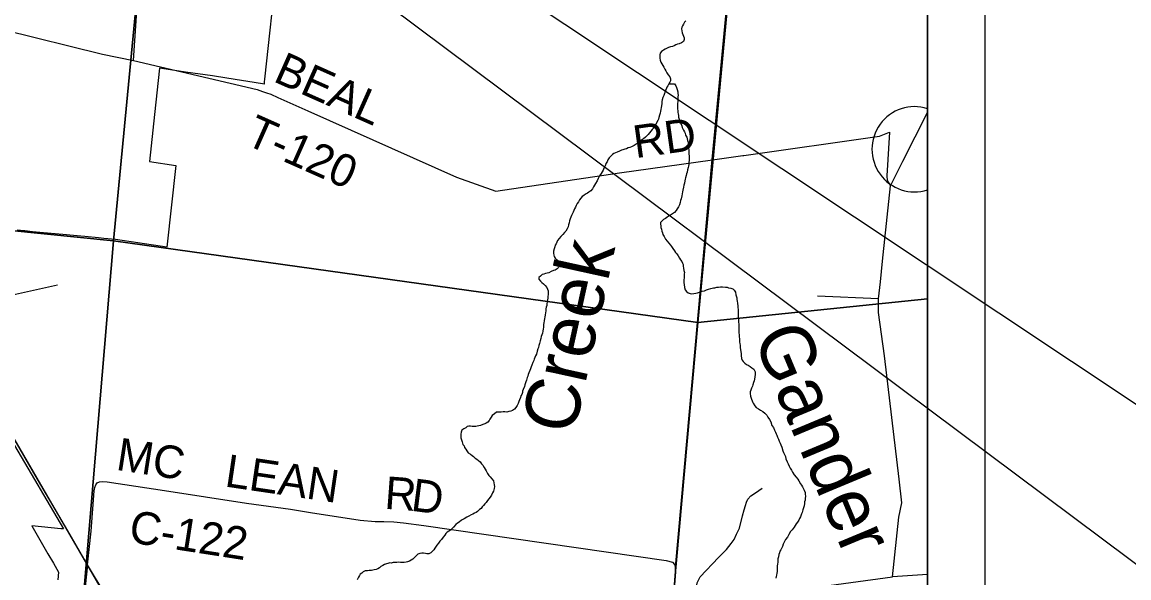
# Model space of a CAD drawing. Extents: x -7.3 to 34, y 0 to 22.
# Drawn here: x 7.321 to 9.251, y 15.258 to 16.227 of the extents above; entities that cross this region are included whole.
import ezdxf

# ---------------------------------------------------------------- set-up
doc = ezdxf.new("R2010")
doc.units = 0
for name, color, linetype in [('GM_X_City_Street', 7, 'Continuous'), ('GM_X_Corporation', 7, 'Continuous'), ('GM_X_County_Road', 7, 'Continuous'), ('GM_X_County_Road_Text', 7, 'Continuous'), ('GM_X_Minor_River', 7, 'Continuous'), ('GM_X_Minor_River_Text', 7, 'Continuous'), ('GM_X_Rail_Line', 7, 'Continuous'), ('GM_X_State_Route', 7, 'Continuous'), ('GM_X_Township_Road', 7, 'Continuous'), ('GM_X_Township_Road_Text', 7, 'Continuous'), ('GM_X_Township_Text', 7, 'Continuous'), ('GM_X_Unincorporated_Location', 7, 'Continuous'), ('SH_Data', 7, 'Continuous'), ('SH_Text', 7, 'Continuous')]:
    doc.layers.add(name, color=color, linetype=linetype)

msp = doc.modelspace()

# ---------------------------------------------------------------- linework, layer by layer
at = {"layer": 'GM_X_City_Street'}
for points in [[(7.515, 16.1606), (7.5352, 16.4637), (7.5353, 16.4644), (7.5529, 16.6394)], [(6.8397, 16.3042), (6.9163, 16.2969), (6.9632, 16.2927), (6.978, 16.2913), (6.9879, 16.2949), (6.9944, 16.3002), (7, 16.3085), (7.0054, 16.3187), (7.0196, 16.3167), (7.0985, 16.2937), (7.1289, 16.2841), (7.1663, 16.2709), (7.1875, 16.2621), (7.2672, 16.2205), (7.2871, 16.2145), (7.4609, 16.1716), (7.515, 16.1606)]]:
    msp.add_lwpolyline(points, dxfattribs=at)
at = {"layer": 'GM_X_Corporation'}
for points in [[(8.9, 14.1), (8.9, 19.7858), (8.8913, 19.7872), (7.8469, 19.8978), (7.6051, 19.9224), (6.9988, 19.9839), (6.9507, 19.9888), (6.4242, 20.0024), (6.4154, 20.0027), (6.0763, 20.0096), (6.0677, 20.0098), (6.0214, 20.0108), (5.9388, 20.0125), (5.8024, 20.0153), (4.9519, 20.0328), (4.9401, 20.0331), (4.9235, 20.0334), (4.7954, 20.036), (4.4762, 20.0428), (4.2328, 20.0479), (4.2288, 20.048), (2.7422, 20.0783)], [(8.9, 14.1), (8.9, 19.3924)], [(8.6707, 17.5268), (8.6269, 17.0745), (8.6205, 17.0074), (8.6201, 16.9946), (8.6191, 16.9835), (8.5243, 15.9875), (8.46, 15.2759), (8.4601, 15.2687), (8.4562, 15.2161)], [(8.4562, 15.2161), (8.4601, 15.2687), (8.46, 15.2759), (8.5243, 15.9875), (8.6191, 16.9835), (8.6201, 16.9946), (8.6205, 17.0074), (8.6269, 17.0745), (8.6707, 17.5268)], [(7.7646, 16.3262), (7.7435, 16.1277), (7.743, 16.123), (7.7427, 16.1193), (7.7398, 16.1197), (7.6775, 16.1295), (7.6527, 16.1334), (7.6058, 16.1398), (7.5868, 16.1429), (7.583, 16.1435), (7.5793, 16.1441), (7.5603, 16.1472), (7.5517, 16.0661), (7.5429, 15.984), (7.5888, 15.9773), (7.573, 15.8344), (7.4836, 15.8479), (7.4632, 15.8499), (7.4537, 15.8507), (7.4301, 15.853), (7.4166, 15.8542), (7.3913, 15.8566), (7.3781, 15.8578), (7.3648, 15.8591), (7.3516, 15.8603), (7.3384, 15.8615), (7.3252, 15.8628), (7.3244, 15.8629), (7.312, 15.864)], [(7.3075, 15.4887), (7.3926, 15.3428), (7.388, 15.3433), (7.3373, 15.3484), (7.3656, 15.2997), (7.3751, 15.2833), (7.3841, 15.2677), (7.3828, 15.254)]]:
    msp.add_lwpolyline(points, dxfattribs=at)
for points in [[(7.5781, 16.8709), (7.4799, 15.8457), (6.4371, 15.9508), (6.5281, 16.9583)], [(8.5942, 16.7168), (8.4992, 15.7029), (7.4799, 15.8457), (7.5781, 16.8709)], [(8.9, 15.7443), (8.9, 16.7566), (8.5942, 16.7168), (8.4992, 15.7029)], [(6.4371, 15.9508), (7.4799, 15.8457), (7.3939, 14.8252), (6.3438, 14.9266)], [(7.4799, 15.8457), (8.4992, 15.7029), (8.4066, 14.6743), (7.3939, 14.8252)], [(8.9, 14.7231), (8.9, 15.7443), (8.4992, 15.7029), (8.4066, 14.6743)]]:
    msp.add_lwpolyline(points, close=True, dxfattribs=at)
at = {"layer": 'GM_X_County_Road'}
for points in [[(7.4344, 15.2802), (7.4407, 15.3391), (7.4465, 15.4096), (7.4474, 15.4153), (7.4491, 15.4201), (7.4516, 15.4234), (7.4554, 15.425), (7.4599, 15.4256), (7.4688, 15.4252), (7.5687, 15.4099), (7.7121, 15.3879), (7.7885, 15.3774), (7.8235, 15.3715), (7.9102, 15.3583), (7.9361, 15.3559), (7.9516, 15.3559), (7.9688, 15.3553), (7.9859, 15.3538), (8.0212, 15.3491), (8.444, 15.2881), (8.4549, 15.285), (8.4585, 15.2807), (8.4599, 15.2763)], [(7.4344, 15.2802), (7.4256, 15.1989), (7.4002, 14.9537), (7.3569, 14.4092), (7.3329, 14.1292), (7.3296, 14.1)], [(8.4599, 15.2763), (8.4602, 15.2754), (8.4603, 15.2681), (8.4564, 15.2156)]]:
    msp.add_lwpolyline(points, dxfattribs=at)
at = {"layer": 'GM_X_Minor_River'}
for points in [[(8.478, 16.2297), (8.4757, 16.2271), (8.4741, 16.224), (8.4722, 16.2211), (8.4714, 16.2184), (8.4709, 16.2158), (8.4712, 16.2123), (8.4719, 16.2085), (8.473, 16.2055), (8.4741, 16.2028), (8.4751, 16.2001), (8.4754, 16.1967), (8.4739, 16.1937), (8.4704, 16.1911), (8.4666, 16.1896), (8.4635, 16.1886), (8.4608, 16.1875), (8.4578, 16.186), (8.4547, 16.185), (8.4516, 16.1839), (8.4482, 16.1828), (8.4455, 16.1817), (8.4421, 16.1803), (8.439, 16.1785), (8.4355, 16.1759), (8.4336, 16.1729), (8.4328, 16.1702), (8.4331, 16.1668), (8.4326, 16.1642), (8.4337, 16.1607), (8.4347, 16.1573), (8.4362, 16.1546), (8.438, 16.1515), (8.4399, 16.1484), (8.4417, 16.145), (8.4435, 16.1423), (8.4453, 16.1388), (8.4475, 16.1353), (8.4501, 16.1319), (8.4516, 16.1284), (8.4515, 16.125), (8.4503, 16.1224), (8.4487, 16.1194), (8.4468, 16.1164), (8.4448, 16.1137), (8.444, 16.1103), (8.442, 16.1073), (8.4408, 16.1028), (8.4396, 16.0994), (8.4383, 16.096), (8.4371, 16.0919), (8.4363, 16.0885), (8.4362, 16.0851), (8.4358, 16.0813), (8.4353, 16.0782), (8.4345, 16.0748), (8.434, 16.0718), (8.4332, 16.0684), (8.432, 16.065), (8.4311, 16.0609), (8.4303, 16.0582), (8.4291, 16.0556), (8.4271, 16.0518), (8.4252, 16.0477), (8.4228, 16.0436), (8.4197, 16.0402), (8.4173, 16.0368), (8.415, 16.0339), (8.4127, 16.0312), (8.4076, 16.0264), (8.4042, 16.0238), (8.4011, 16.0212), (8.3984, 16.0186), (8.3945, 16.0161), (8.3918, 16.0142), (8.3883, 16.012), (8.3834, 16.0095), (8.3803, 16.0084), (8.3776, 16.0077), (8.3746, 16.0062), (8.3719, 16.0055), (8.3685, 16.0045), (8.3658, 16.0038), (8.3623, 16.0023), (8.3585, 16.0005)], [(8.4487, 16.1194), (8.4582, 16.1195), (8.4608, 16.1164), (8.4622, 16.113), (8.4633, 16.1095), (8.464, 16.1057), (8.4643, 16.1027), (8.4646, 16.1), (8.4642, 16.097), (8.4645, 16.0932), (8.464, 16.0894), (8.4635, 16.0848), (8.4634, 16.0814), (8.4638, 16.0788), (8.4637, 16.0757), (8.464, 16.0727), (8.4643, 16.0696), (8.4646, 16.067), (8.4653, 16.0643), (8.4657, 16.0616), (8.4667, 16.0578), (8.4678, 16.0547), (8.4689, 16.0513), (8.471, 16.0463), (8.4721, 16.0436), (8.4743, 16.039), (8.4757, 16.036), (8.4768, 16.0333), (8.4779, 16.0302), (8.4797, 16.0264), (8.4804, 16.0237), (8.4811, 16.021), (8.4822, 16.0176), (8.4824, 16.0134), (8.4831, 16.01), (8.4831, 16.0069), (8.4834, 16.0043), (8.4837, 16.0001), (8.4836, 15.997), (8.4839, 15.994), (8.4842, 15.989), (8.4841, 15.9864), (8.4837, 15.9822), (8.4832, 15.9788), (8.4828, 15.9762), (8.482, 15.9735), (8.4811, 15.9694), (8.4803, 15.9652), (8.4794, 15.9625), (8.479, 15.9599), (8.4778, 15.9557), (8.4773, 15.9531), (8.4765, 15.9505), (8.4757, 15.9463), (8.4748, 15.9429), (8.474, 15.9395), (8.4728, 15.9342), (8.4723, 15.9312), (8.4719, 15.9278), (8.471, 15.924), (8.4701, 15.9191), (8.4689, 15.916), (8.4681, 15.9126), (8.4669, 15.9085), (8.4653, 15.9051), (8.4633, 15.9014), (8.4614, 15.8987), (8.4586, 15.895), (8.4552, 15.8928), (8.4517, 15.8906), (8.4479, 15.8884), (8.4452, 15.8865), (8.4425, 15.8847), (8.4394, 15.8829), (8.4367, 15.8803), (8.4343, 15.8777), (8.4343, 15.8746), (8.4346, 15.872), (8.4349, 15.8689), (8.4356, 15.8659), (8.4363, 15.8624), (8.4374, 15.8594), (8.4381, 15.8567), (8.4403, 15.8532), (8.4428, 15.8486), (8.4458, 15.8451), (8.4487, 15.8413), (8.4517, 15.8382), (8.4535, 15.8355), (8.4554, 15.8324), (8.4583, 15.8281), (8.4601, 15.8254), (8.4624, 15.8227), (8.4646, 15.8196), (8.4671, 15.8154), (8.469, 15.8127), (8.4712, 15.8096), (8.4723, 15.8069), (8.4733, 15.8043), (8.4736, 15.8012), (8.4743, 15.7978)], [(8.3585, 16.0005), (8.3558, 15.9994), (8.3528, 15.998), (8.3501, 15.9965), (8.3466, 15.9928), (8.3446, 15.9902), (8.3423, 15.9868), (8.3411, 15.9834), (8.3387, 15.9804), (8.3379, 15.9778), (8.3367, 15.9751), (8.3351, 15.9725), (8.3339, 15.9691), (8.332, 15.9661), (8.3304, 15.9631), (8.3276, 15.959), (8.3253, 15.9545), (8.3233, 15.9504), (8.3209, 15.9455), (8.3189, 15.9425), (8.3174, 15.9398), (8.3154, 15.9365), (8.3127, 15.9331), (8.3092, 15.9305), (8.3065, 15.9287), (8.3034, 15.9269), (8.3004, 15.925), (8.2973, 15.9232), (8.2949, 15.9202), (8.293, 15.9172), (8.291, 15.9138), (8.2887, 15.9105), (8.2871, 15.9071), (8.2859, 15.9044), (8.2843, 15.9014), (8.2827, 15.8984), (8.2819, 15.8958), (8.2807, 15.8932), (8.2787, 15.8898), (8.2775, 15.8871), (8.2763, 15.8841), (8.2755, 15.8807), (8.2747, 15.8773), (8.2734, 15.8736), (8.273, 15.8701), (8.2714, 15.8664), (8.269, 15.8626), (8.2667, 15.86), (8.2636, 15.8567), (8.2601, 15.8533), (8.257, 15.8496), (8.2546, 15.8462), (8.2531, 15.8432), (8.2519, 15.8406), (8.2503, 15.838), (8.2495, 15.8349), (8.2483, 15.8316), (8.2474, 15.8278), (8.2473, 15.8244), (8.248, 15.8209), (8.2487, 15.8182), (8.2502, 15.8156), (8.2535, 15.8124), (8.2557, 15.8094), (8.2576, 15.8059), (8.2579, 15.8025), (8.2563, 15.7991), (8.2536, 15.7965), (8.2501, 15.7947), (8.2474, 15.7936), (8.2432, 15.7922), (8.2394, 15.79), (8.2363, 15.7893), (8.2337, 15.7886), (8.2306, 15.7875), (8.2279, 15.7868), (8.2245, 15.7842), (8.2221, 15.7816), (8.2217, 15.7786), (8.2246, 15.7751), (8.2273, 15.7731), (8.2302, 15.7704), (8.2328, 15.7677), (8.2358, 15.7642), (8.2372, 15.7611), (8.2379, 15.7585), (8.2382, 15.755), (8.2382, 15.7516), (8.2377, 15.749), (8.2373, 15.7456), (8.2368, 15.7425), (8.2364, 15.7391), (8.2359, 15.7357), (8.2355, 15.7327), (8.2347, 15.7297), (8.2342, 15.727), (8.2341, 15.7236), (8.2333, 15.7202), (8.2328, 15.7164), (8.232, 15.7126), (8.2316, 15.71)], [(8.4743, 15.7978), (8.475, 15.794), (8.4757, 15.7905), (8.4756, 15.7879), (8.4756, 15.7845), (8.4751, 15.781), (8.475, 15.7776), (8.475, 15.775), (8.4749, 15.7723), (8.4752, 15.7696), (8.4759, 15.7643), (8.4773, 15.7601), (8.4795, 15.757), (8.4821, 15.7547), (8.4855, 15.7535), (8.4881, 15.753), (8.4923, 15.7537), (8.4958, 15.7544), (8.4984, 15.7547), (8.5042, 15.7565), (8.5068, 15.7576), (8.5106, 15.7586), (8.5141, 15.7601), (8.5175, 15.7611), (8.5221, 15.7622), (8.5263, 15.7636), (8.529, 15.7639), (8.5324, 15.7646), (8.5354, 15.7649), (8.5385, 15.7652), (8.5419, 15.7652), (8.5472, 15.765), (8.5502, 15.7646), (8.5529, 15.7638), (8.5566, 15.7633), (8.56, 15.7621), (8.5626, 15.7598), (8.5648, 15.7559), (8.5655, 15.7517), (8.5669, 15.7464), (8.5672, 15.7437), (8.5679, 15.7399), (8.5682, 15.7372), (8.5688, 15.7308), (8.5694, 15.7243), (8.5694, 15.7209), (8.5697, 15.7163), (8.5696, 15.7125), (8.5699, 15.7083), (8.5701, 15.7041), (8.5704, 15.6996), (8.5704, 15.6969), (8.5706, 15.6901), (8.5709, 15.687), (8.5711, 15.6798), (8.5717, 15.673), (8.572, 15.6691), (8.5724, 15.6665), (8.5727, 15.6631), (8.573, 15.6593), (8.5733, 15.6554), (8.574, 15.6524), (8.5746, 15.6482), (8.5749, 15.6455), (8.5756, 15.6402), (8.5767, 15.6375), (8.5785, 15.6348), (8.5811, 15.6321), (8.5841, 15.6298), (8.5871, 15.6286), (8.5904, 15.6262), (8.5934, 15.6242), (8.5968, 15.6215), (8.599, 15.6169), (8.5993, 15.6127), (8.5988, 15.6078), (8.5975, 15.6014), (8.5963, 15.5983), (8.5951, 15.5946), (8.5943, 15.5919), (8.593, 15.5885), (8.5918, 15.5851), (8.5906, 15.5821), (8.5902, 15.5795), (8.5908, 15.5745), (8.5919, 15.5711), (8.5944, 15.5649), (8.5955, 15.5623), (8.5988, 15.5576), (8.601, 15.5549), (8.6048, 15.5522), (8.6085, 15.5502), (8.6126, 15.5478), (8.616, 15.5451), (8.6193, 15.5416), (8.6215, 15.5381), (8.6241, 15.5339), (8.6263, 15.5297), (8.6284, 15.5232), (8.631, 15.5201), (8.6328, 15.5151)], [(8.2316, 15.71), (8.2311, 15.7062), (8.2306, 15.7024), (8.2302, 15.6997), (8.2302, 15.6971), (8.2297, 15.6944), (8.2293, 15.6918), (8.2288, 15.688), (8.228, 15.6846), (8.2272, 15.6819), (8.226, 15.6786), (8.2251, 15.6755), (8.2243, 15.6714), (8.223, 15.6665), (8.2218, 15.6631), (8.2214, 15.6597), (8.2202, 15.657), (8.2189, 15.6529), (8.2177, 15.648), (8.2161, 15.645), (8.2149, 15.6419), (8.2137, 15.6393), (8.2129, 15.6367), (8.2113, 15.6333), (8.2097, 15.6288), (8.2085, 15.6257), (8.2073, 15.6224), (8.2061, 15.6193), (8.2045, 15.6152), (8.2033, 15.6122), (8.2025, 15.6095), (8.2016, 15.6069), (8.2004, 15.6024), (8.1992, 15.5997), (8.1976, 15.5941), (8.1971, 15.5914), (8.1947, 15.5862), (8.1935, 15.5835), (8.1931, 15.5809), (8.1919, 15.5775), (8.1903, 15.5749), (8.1899, 15.5722), (8.1879, 15.5684), (8.1867, 15.5651), (8.1855, 15.562), (8.1839, 15.5583), (8.1819, 15.5549), (8.1796, 15.5519), (8.1761, 15.5497), (8.1731, 15.5486), (8.1696, 15.5476), (8.1658, 15.5469), (8.1624, 15.547), (8.1594, 15.547), (8.1559, 15.5467), (8.1533, 15.5468), (8.1506, 15.5468), (8.148, 15.5465), (8.1445, 15.5439), (8.1403, 15.5406), (8.1387, 15.538), (8.1363, 15.5346), (8.1351, 15.532), (8.1328, 15.5294), (8.1301, 15.5272), (8.1274, 15.5261), (8.124, 15.525), (8.1198, 15.5236), (8.1171, 15.5229), (8.1144, 15.5222), (8.1118, 15.5219), (8.1091, 15.5215), (8.1053, 15.5216), (8.1027, 15.522), (8.0997, 15.5221), (8.097, 15.5218), (8.0943, 15.5196), (8.0908, 15.5177), (8.0877, 15.5152), (8.0865, 15.5118), (8.0857, 15.508), (8.0856, 15.5046), (8.0859, 15.5019), (8.087, 15.4981), (8.0881, 15.495), (8.0895, 15.4904), (8.0913, 15.4877), (8.0924, 15.485), (8.0942, 15.482), (8.0961, 15.4789), (8.0986, 15.4758), (8.1024, 15.4734), (8.1054, 15.4711), (8.108, 15.4691), (8.111, 15.4664), (8.1136, 15.4648), (8.1166, 15.4621), (8.1192, 15.4598), (8.1221, 15.4567), (8.1243, 15.454), (8.1265, 15.4501)], [(8.6328, 15.5151), (8.6346, 15.512), (8.6357, 15.509), (8.6371, 15.5063), (8.6382, 15.5032), (8.6397, 15.4998), (8.6411, 15.4963), (8.6429, 15.4925), (8.644, 15.4894), (8.6454, 15.4856), (8.6475, 15.4791), (8.6486, 15.476), (8.6508, 15.4718), (8.6519, 15.4691), (8.6529, 15.4653), (8.6551, 15.4599), (8.6565, 15.4565), (8.6583, 15.4523), (8.6602, 15.4492), (8.6628, 15.4457), (8.6642, 15.4422), (8.6671, 15.4376), (8.6704, 15.4334), (8.6738, 15.4299), (8.6756, 15.4268), (8.6782, 15.4218), (8.68, 15.4191), (8.6818, 15.4164), (8.6837, 15.413), (8.6847, 15.4103), (8.6862, 15.4064), (8.6865, 15.4034), (8.6868, 15.4003), (8.6863, 15.3958), (8.6863, 15.3931), (8.6854, 15.3901), (8.685, 15.3875), (8.6845, 15.3833), (8.6833, 15.3795), (8.6825, 15.3761), (8.6809, 15.3716), (8.68, 15.369), (8.678, 15.3641), (8.6765, 15.3611), (8.6753, 15.358), (8.6729, 15.3547), (8.6706, 15.3517), (8.669, 15.3491), (8.667, 15.3461), (8.6635, 15.3416), (8.6608, 15.3382), (8.658, 15.3333), (8.6553, 15.3288), (8.6521, 15.3244), (8.6506, 15.321), (8.6478, 15.3161), (8.6466, 15.3123), (8.6454, 15.3097), (8.6438, 15.3067), (8.6422, 15.3041), (8.6414, 15.3014), (8.6406, 15.2984), (8.6397, 15.2942), (8.6389, 15.2905), (8.6388, 15.2874), (8.6384, 15.2848), (8.6379, 15.2814), (8.6375, 15.2783), (8.6374, 15.2745), (8.6373, 15.2719), (8.6373, 15.2685), (8.6368, 15.2658), (8.6364, 15.2624), (8.6356, 15.2598), (8.6351, 15.2571)], [(8.1265, 15.4501), (8.1284, 15.447), (8.1302, 15.444), (8.1324, 15.4397), (8.1346, 15.4363), (8.1368, 15.4336), (8.1398, 15.4304), (8.1427, 15.427), (8.1434, 15.4235), (8.1441, 15.4201), (8.1444, 15.4167), (8.1439, 15.4133), (8.1427, 15.4087), (8.1411, 15.4057), (8.1395, 15.402), (8.1372, 15.3986), (8.1348, 15.3956), (8.1321, 15.3926), (8.1301, 15.3892), (8.1274, 15.3866), (8.1255, 15.384), (8.1231, 15.3814), (8.1212, 15.3784), (8.1181, 15.3766), (8.115, 15.3736), (8.1123, 15.3718), (8.1096, 15.3703), (8.1069, 15.3689), (8.1039, 15.3678), (8.1, 15.3652), (8.0962, 15.3634), (8.0916, 15.3608), (8.087, 15.3583), (8.0827, 15.3549), (8.0797, 15.3527), (8.077, 15.3505), (8.0731, 15.346), (8.0704, 15.3438), (8.0676, 15.3408), (8.0649, 15.339), (8.0622, 15.3372), (8.0595, 15.3349), (8.058, 15.3323), (8.0549, 15.3286), (8.0521, 15.3245), (8.0494, 15.3215), (8.0467, 15.3181), (8.0439, 15.3148), (8.0404, 15.3095), (8.0388, 15.3065), (8.0365, 15.3039), (8.0334, 15.3013), (8.0299, 15.2995), (8.0265, 15.2996), (8.0239, 15.3), (8.0205, 15.3004), (8.0178, 15.3009), (8.0144, 15.3002), (8.0106, 15.2988), (8.0079, 15.2958), (8.0052, 15.2932), (8.0021, 15.2902), (7.9994, 15.2884), (7.9963, 15.2865), (7.9928, 15.2855), (7.9902, 15.2848), (7.9868, 15.2845), (7.9833, 15.2842), (7.9807, 15.2842), (7.9777, 15.2847), (7.9742, 15.2844), (7.9708, 15.2844), (7.9678, 15.2841), (7.9644, 15.2834), (7.9617, 15.2835), (7.9587, 15.2828), (7.956, 15.2821), (7.9525, 15.281), (7.9495, 15.2792), (7.946, 15.2774), (7.9437, 15.2748), (7.941, 15.2733), (7.9379, 15.2722), (7.9345, 15.2715), (7.9299, 15.2705), (7.9261, 15.2702), (7.9227, 15.2699), (7.9189, 15.2696), (7.9155, 15.2682), (7.9128, 15.2659), (7.9101, 15.2641), (7.9089, 15.2615), (7.9073, 15.2588), (7.9049, 15.2543)]]:
    msp.add_lwpolyline(points, dxfattribs=at)
at = {"layer": 'GM_X_Rail_Line'}
msp.add_lwpolyline([(8.1171, 14.1), (7.77, 14.7008), (7.4272, 15.293), (6.5394, 16.8246), (6.3886, 17.0851), (6.2996, 17.2555), (6.2775, 17.3138), (6.2567, 17.3864), (6.213, 17.5514), (6.1948, 17.6035), (6.1703, 17.6358), (6.1218, 17.6697), (5.9568, 17.7678)], dxfattribs=at)
at = {"layer": 'GM_X_State_Route'}
for points in [[(7.4344, 15.2802), (7.4005, 15.3393), (7.3473, 15.4297), (7.2956, 15.5194), (7.2506, 15.5959), (7.2007, 15.6815), (7.1784, 15.724), (7.1181, 15.8285)], [(8.0558, 14.2031), (8.0084, 14.2839), (7.9897, 14.3165), (7.9577, 14.3718), (7.9127, 14.4514), (7.8775, 14.5131), (7.8704, 14.526), (7.7981, 14.651), (7.748, 14.7378), (7.707, 14.8101), (7.664, 14.8848), (7.6231, 14.9559), (7.5815, 15.0273), (7.5477, 15.0857), (7.4974, 15.1731), (7.4652, 15.2288), (7.4344, 15.2802)]]:
    msp.add_lwpolyline(points, dxfattribs=at)
at = {"layer": 'GM_X_Township_Road'}
for p, q in [((8.8177, 15.7742), (8.8213, 15.8101)), ((7.1784, 15.724), (7.3824, 15.7687)), ((8.8145, 15.7443), (8.7081, 15.7491)), ((8.9, 15.2633), (8.8388, 15.2593))]:
    msp.add_line(p, q, dxfattribs=at)
for points in [[(7.515, 16.1606), (7.7308, 16.1096), (7.7399, 16.1064), (7.747, 16.1039)], [(7.747, 16.1039), (7.7541, 16.1013), (7.7663, 16.0959)], [(7.7663, 16.0959), (7.819, 16.0725), (8.0781, 15.9565), (8.147, 15.9325), (8.3625, 15.9641), (8.5246, 15.987), (8.5775, 15.9945), (8.5796, 15.9948)], [(8.8213, 15.8101), (8.8224, 15.8213), (8.8354, 15.9416), (8.857, 15.9844), (8.9, 16.0695)], [(8.5796, 15.9948), (8.8163, 16.0283), (8.8336, 16.0352), (8.8286, 15.9589), (8.8296, 15.9509), (8.8354, 15.9416)], [(8.8388, 15.2593), (8.8497, 15.3632), (8.8547, 15.3886), (8.8505, 15.4298), (8.8246, 15.6447), (8.8141, 15.7206), (8.8145, 15.7443), (8.8177, 15.7742)], [(8.4991, 15.2202), (8.496, 15.236), (8.498, 15.2488), (8.5034, 15.2591), (8.5354, 15.2929), (8.5493, 15.307), (8.5573, 15.3172), (8.5625, 15.3244), (8.5665, 15.3336), (8.5716, 15.3445), (8.5773, 15.3659), (8.5801, 15.376), (8.5821, 15.3838), (8.5838, 15.3896), (8.5863, 15.395), (8.5918, 15.4005), (8.5996, 15.4057), (8.6113, 15.414)], [(8.4564, 15.2156), (8.4991, 15.2202), (8.5311, 15.2224), (8.6803, 15.238), (8.8388, 15.2593)]]:
    msp.add_lwpolyline(points, dxfattribs=at)
at = {"layer": 'GM_X_Township_Text'}
msp.add_line((8.9, 15.9345), (8.9, 16.0763), dxfattribs=at)
msp.add_arc((8.8773, 16.0054), 0.0744, 72.2745, 287.7255, dxfattribs=at)
at = {"layer": 'GM_X_Unincorporated_Location'}
msp.add_line((8.8773, 16.0054), (8.8773, 16.0054), dxfattribs=at)
at = {"layer": 'SH_Data'}
for p, q in [((9, 21), (9, 14)), ((8.9, 20.9), (8.9, 14.1))]:
    msp.add_line(p, q, dxfattribs=at)
at = {"layer": 'SH_Text'}
msp.add_lwpolyline([(9.4026, 15.1778), (9.4027, 15.4673), (5.869, 17.8194)], close=True, dxfattribs=at)

# ---------------------------------------------------------------- texts
at = {"layer": 'GM_X_County_Road_Text'}
for s, height, rotation, p in [('MC', 0.05682, 351.1164, (7.4827, 15.4463)), ('LEAN', 0.05682, 351.598, (7.6724, 15.4172)), ('R', 0.0568, 355.7498, (7.9515, 15.3782)), ('D', 0.0568, 352.6066, (7.9972, 15.3749)), ('C-122', 0.05682, 351.1691, (7.5049, 15.32))]:
    msp.add_text(s, height=height, rotation=rotation, dxfattribs=at).set_placement(p)
at = {"layer": 'GM_X_Minor_River_Text'}
for s, rotation, p in [('Creek', 77.5953, (8.2829, 15.5047)), ('Gander', 292.6699, (8.5943, 15.6787))]:
    msp.add_text(s, height=0.09468, rotation=rotation, dxfattribs=at).set_placement(p)
at = {"layer": 'GM_X_Township_Road_Text'}
for s, rotation, p in [('BEAL', 336.0133, (7.7566, 16.1247)), ('T-120', 336.0668, (7.7069, 16.0152)), ('RD', 7.924, (8.3904, 15.9898))]:
    msp.add_text(s, height=0.05682, rotation=rotation, dxfattribs=at).set_placement(p)

doc.saveas('drawing.dxf')
